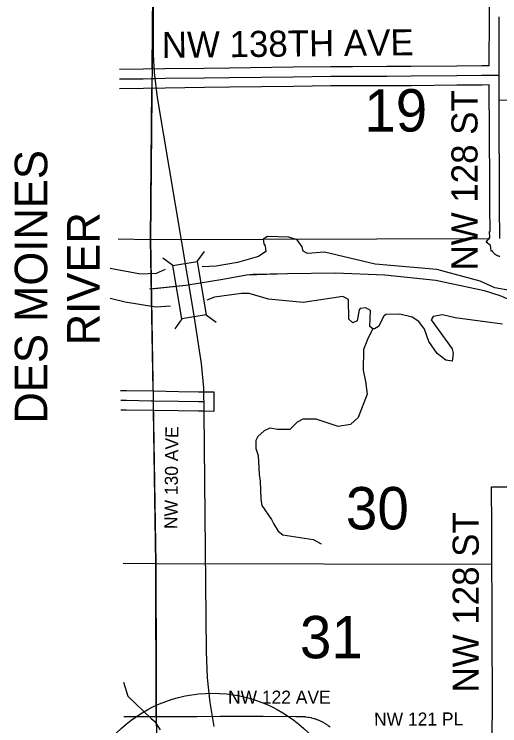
# Model space of a CAD drawing. Extents: x -1403959 to 81668, y -1400582 to 11018.
# Drawn here: x 6176.3 to 6320.4, y 9558.5 to 9769.7 of the extents above; entities that cross this region are included whole.
import ezdxf

# ---------------------------------------------------------------- set-up
doc = ezdxf.new("R2010")
doc.units = 0
for name, color, linetype in [('tdCiCityStreetTxt', 7, 'Continuous'), ('tdCiMapFrame', 7, 'Continuous'), ('tdCiSectLine', 7, 'Continuous'), ('tdCoCityStreetMajor', 7, 'Continuous'), ('tdCoCityStreetMinor', 7, 'Continuous'), ('tdCoClipBndry', 7, 'Continuous'), ('tdCoSecRteCL', 7, 'Continuous'), ('tdCoSectLinePart', 7, 'Continuous'), ('tdCoSectNmbr', 7, 'Continuous'), ('tdCoSurfAsphalt', 7, 'Continuous'), ('tdCoSurfBitum', 7, 'Continuous'), ('tdCoSurfConc', 7, 'Continuous'), ('tdCoTwpNameTxt', 7, 'Continuous')]:
    doc.layers.add(name, color=color, linetype=linetype)

msp = doc.modelspace()

# ---------------------------------------------------------------- linework, layer by layer
at = {"layer": 'tdCiCityStreetTxt'}
for p, q in [((6230.61, 9696.34), (6232.73, 9699.32)), ((6223.4, 9695.14), (6220.42, 9697.26)), ((6223.4, 9695.14), (6230.61, 9696.34)), ((6230.61, 9696.34), (6233.26, 9680.48)), ((6226.05, 9679.27), (6223.4, 9695.14)), ((6223.4, 9695.14), (6223.4, 9695.14)), ((6226.05, 9679.27), (6223.93, 9676.3)), ((6233.26, 9680.48), (6226.05, 9679.27)), ((6233.26, 9680.48), (6236.24, 9678.35))]:
    msp.add_line(p, q, dxfattribs=at)
at = {"layer": 'tdCiMapFrame'}
for points in [[(6320.44, 9703.12), (6320.36, 9712.55), (6320.21, 9744.27), (6320.2, 9751.51), (6320.2, 9751.61), (6320.23, 9768.93)], [(6217.23, 9750.63), (6218.02, 9750.65), (6218.06, 9750.65), (6221.06, 9750.7), (6232.75, 9750.84), (6240.17, 9750.94), (6259.13, 9751.18), (6270.28, 9751.32), (6276.67, 9751.35), (6286.88, 9751.38), (6294.08, 9751.41), (6307.68, 9751.53), (6315.14, 9751.59), (6317.22, 9751.62), (6320.2, 9751.61)], [(6207.52, 9750.53), (6208.5, 9750.53), (6214.6, 9750.59), (6217.23, 9750.63)], [(6320.21, 9744.27), (6329.06, 9743.99)], [(6207.88, 9655.13), (6208.5, 9655.13), (6209.56, 9655.13), (6216.91, 9655)], [(6216.91, 9655), (6217.58, 9654.99)], [(6217.58, 9654.99), (6217.65, 9654.99), (6225.03, 9654.86), (6230.99, 9654.77), (6232.63, 9654.75)]]:
    msp.add_lwpolyline(points, dxfattribs=at)
at = {"layer": 'tdCiSectLine'}
for points in [[(6207.55, 9753.43), (6214.56, 9753.49), (6221.01, 9753.6), (6221.02, 9753.6), (6232.71, 9753.74), (6240.14, 9753.84), (6240.14, 9753.84), (6259.09, 9754.08), (6270.24, 9754.22), (6270.26, 9754.22), (6276.65, 9754.25), (6276.66, 9754.25), (6286.87, 9754.29), (6294.06, 9754.32), (6307.65, 9754.43), (6315.1, 9754.49), (6317.18, 9754.52), (6317.22, 9754.52), (6317.24, 9754.52), (6317.3, 9754.52), (6317.33, 9768.94), (6317.34, 9771.84)], [(6320.48, 9697.76), (6320.29, 9697.8), (6320.11, 9697.85), (6319.93, 9697.92), (6319.79, 9697.99), (6319.62, 9698.07), (6319.59, 9698.08), (6319.42, 9698.17), (6319.26, 9698.27), (6319.11, 9698.38), (6319, 9698.47), (6318.86, 9698.59), (6318.82, 9698.62), (6318.68, 9698.75), (6318.55, 9698.89), (6318.43, 9699.03), (6318.36, 9699.14), (6318.25, 9699.29), (6318.22, 9699.34), (6318.15, 9699.44), (6317.84, 9699.41), (6317.75, 9700.4), (6317.72, 9700.56), (6317.69, 9700.75), (6317.68, 9700.84), (6317.66, 9701.02), (6317.65, 9701.06), (6316.42, 9702.02), (6317.5, 9703.42), (6317.35, 9705.19), (6317.52, 9705.21), (6317.46, 9712.53), (6317.46, 9712.54), (6317.32, 9741.37), (6317.31, 9741.37), (6317.31, 9741.46), (6317.22, 9741.47), (6317.31, 9744.31), (6317.29, 9747.16), (6317.3, 9747.16), (6317.3, 9748.71), (6317.29, 9748.71), (6317.29, 9748.72), (6317.23, 9748.72), (6315.18, 9748.69), (6315.16, 9748.69), (6307.7, 9748.62), (6307.7, 9748.62), (6294.11, 9748.51), (6294.09, 9748.51), (6286.89, 9748.48), (6286.89, 9748.48), (6276.68, 9748.45), (6270.3, 9748.42), (6259.17, 9748.27), (6259.16, 9748.27), (6240.21, 9748.04), (6232.78, 9747.94), (6232.78, 9747.94), (6221.1, 9747.8), (6214.65, 9747.69), (6214.63, 9747.69), (6207.5, 9747.62)], [(6207.83, 9658.03), (6209.56, 9658.03), (6209.61, 9658.03), (6217.7, 9657.89), (6225.08, 9657.76), (6231.03, 9657.67), (6232.65, 9657.65), (6235.55, 9657.63), (6235.5, 9651.82), (6232.6, 9651.85), (6230.97, 9651.86), (6230.95, 9651.86), (6224.98, 9651.96), (6224.98, 9651.96), (6217.6, 9652.09), (6217.6, 9652.09), (6209.53, 9652.23), (6207.93, 9652.23)], [(6318.2, 9556.07), (6318.25, 9564.12), (6318.23, 9571.77), (6318.18, 9580.53), (6318.18, 9580.54), (6318.17, 9588.8), (6318.12, 9596.87), (6318.12, 9596.88), (6318.1, 9605.16), (6318.04, 9612.39), (6318.04, 9612.41), (6318.02, 9620.59), (6317.98, 9626.53), (6317.95, 9629.43), (6323.76, 9629.47)], [(6208.77, 9561.28), (6230.63, 9561.21), (6237.45, 9561.37), (6237.52, 9561.37), (6237.54, 9561.37), (6250.22, 9561.29), (6259.9, 9561.28), (6259.92, 9561.28), (6261.59, 9561.26), (6261.75, 9561.25), (6262.48, 9561.21), (6262.48, 9561.21), (6262.67, 9561.19), (6262.7, 9561.18), (6263.42, 9561.08), (6263.59, 9561.06), (6263.6, 9561.05), (6264.32, 9560.91), (6264.49, 9560.86), (6264.5, 9560.86), (6265.21, 9560.67), (6265.38, 9560.62), (6266.08, 9560.38), (6266.08, 9560.38), (6266.25, 9560.32), (6266.93, 9560.04), (6266.94, 9560.04), (6267.1, 9559.97), (6267.76, 9559.65), (6267.78, 9559.64), (6267.92, 9559.56), (6268.56, 9559.2), (6268.59, 9559.19), (6268.71, 9559.11), (6269.33, 9558.71), (6269.37, 9558.69), (6269.48, 9558.6), (6270.07, 9558.17)]]:
    msp.add_lwpolyline(points, dxfattribs=at)
at = {"layer": 'tdCoCityStreetMajor'}
for points in [[(6217.22, 9753.55), (6217.62, 9799.5)], [(6216.78, 9702.88), (6217.17, 9747.74)], [(6207.11, 9703.04), (6216.78, 9702.88)], [(6216.78, 9702.88), (6317.51, 9703.12)], [(6217.5, 9657.91), (6216.78, 9702.88)], [(6218.33, 9606.68), (6217.6, 9652.11)], [(6208.66, 9606.75), (6218.33, 9606.68)], [(6218.33, 9606.68), (6317.99, 9606.45)], [(6218.33, 9606.68), (6218.44, 9561.27)]]:
    msp.add_lwpolyline(points, dxfattribs=at)
at = {"layer": 'tdCoCityStreetMinor'}
for points in [[(6217.22, 9753.55), (6217.62, 9799.5)], [(6217.5, 9657.91), (6216.78, 9702.88), (6217.17, 9747.74)], [(6218.44, 9561.27), (6218.33, 9606.68), (6217.6, 9652.11)]]:
    msp.add_lwpolyline(points, dxfattribs=at)
at = {"layer": 'tdCoClipBndry'}
for points in [[(6778.71, 10085.37), (6705.52, 10085.58), (6607.92, 10086.06), (6510.34, 10086.5), (6412.84, 10087.26), (6315.56, 10087.31), (6215.78, 10087.65), (6215.21, 10012.23), (6215.81, 9994.41), (6217.04, 9970.57), (6217.41, 9896.62), (6217.06, 9848.03), (6217.62, 9799.5), (6216.78, 9702.88), (6218.33, 9606.68), (6218.57, 9510.16), (6218.52, 9404.76), (6218.61, 9307.34), (6218.13, 9211.25), (6218.14, 9113.22), (6218.14, 9016.46), (6218.02, 8919.84), (6217.44, 8816.34), (6216.99, 8719.3)], [(6217.01, 9688.24), (6227.22, 9689.26), (6238.25, 9691.05), (6245.21, 9692.35), (6257.4, 9692.78), (6271.56, 9693), (6286.3, 9692.31), (6301.47, 9690.76), (6315.83, 9687.72), (6320.39, 9686.18), (6329.92, 9682.23)]]:
    msp.add_lwpolyline(points, dxfattribs=at)
at = {"layer": 'tdCoSecRteCL'}
msp.add_lwpolyline([(6217.64, 9809.12), (6217.49, 9757.74), (6217.86, 9752.44), (6218.72, 9745), (6229.45, 9680.84), (6231.76, 9666.02), (6232.42, 9658.85), (6232.57, 9651.48), (6233.27, 9580.56), (6233.55, 9572.72), (6234.36, 9565.41), (6235.58, 9558.3)], dxfattribs=at)
at = {"layer": 'tdCoSurfAsphalt'}
msp.add_circle((6235.15, 9527.83), 40.33, dxfattribs=at)
at = {"layer": 'tdCoSurfBitum'}
for points in [[(6340.36, 9682.17), (6335.63, 9683.57), (6323.43, 9687.73), (6319, 9688.51), (6314.58, 9690.51), (6301.77, 9693.92), (6283.45, 9695.52), (6268.35, 9699.08), (6263.31, 9698.65), (6262.09, 9699.41), (6261.79, 9700.64), (6260.27, 9702.78), (6257.83, 9703.55), (6251.42, 9703.73), (6250.19, 9702.97), (6250.34, 9701.6), (6250.8, 9700.98), (6250.94, 9699.3), (6248.8, 9697.78), (6242.53, 9695.98), (6236.27, 9694.93), (6232.03, 9694.69)], [(6221.12, 9693.94), (6218.39, 9692.71), (6213.81, 9692.57), (6204.75, 9694.24)], [(6222.7, 9683.01), (6218.36, 9682.79), (6209.2, 9684.2), (6204.75, 9685.35)], [(6282.77, 9676.28), (6281.86, 9677.05), (6282.03, 9681.78), (6280.66, 9682.55), (6278.98, 9682.41), (6278.67, 9681.95), (6278.05, 9678.75), (6276.82, 9678.14), (6275.61, 9679.21), (6275.47, 9685.01), (6273.8, 9685.94), (6262.03, 9684.15), (6251.81, 9685.1), (6246.01, 9686.8), (6243.72, 9686.81), (6235.78, 9685.77), (6233.5, 9684.84)], [(6321.26, 9677.67), (6307.21, 9679.55), (6303.4, 9680.48), (6300.65, 9680.03), (6300.04, 9678.97), (6306.27, 9670.4), (6306.57, 9669.02), (6306.25, 9666.73), (6304.42, 9667.04), (6301.83, 9669.04), (6299.4, 9672.56), (6298.04, 9676.23), (6296.37, 9678.52), (6294.39, 9679.75), (6290.73, 9680.68), (6286.6, 9680.54), (6285.99, 9680.09), (6284.45, 9677.04), (6283.23, 9676.28), (6282.77, 9676.28), (6281.39, 9673.7), (6280, 9670.19), (6279.83, 9664.08), (6280.58, 9660.72), (6281.02, 9656.9), (6278.4, 9650.04), (6276.1, 9647.92), (6272.44, 9647.32), (6265.88, 9649.48), (6261.91, 9649.5), (6260.23, 9648.59), (6258.08, 9646.46), (6254.42, 9646.47), (6252.13, 9646.79), (6250.45, 9646.03), (6248.61, 9644.36), (6247.99, 9643.14), (6247.98, 9640.85), (6248.74, 9638.71), (6249.02, 9633.06), (6249.32, 9631.07), (6249.46, 9625.73), (6249.76, 9623.9), (6252.64, 9619.76), (6253.25, 9618.54), (6254.61, 9616.24), (6255.98, 9615.17), (6264.99, 9613.76), (6267.43, 9612.53)], [(6208.72, 9571.41), (6210, 9567.26), (6217, 9560.51), (6217.92, 9559.9), (6219.59, 9557.3)]]:
    msp.add_lwpolyline(points, dxfattribs=at)
at = {"layer": 'tdCoTwpNameTxt'}
msp.add_lwpolyline([(6216.47, 9688.19), (6227.22, 9689.26), (6238.25, 9691.05), (6245.21, 9692.35), (6247.08, 9692.56), (6257.4, 9692.78), (6271.56, 9693), (6286.3, 9692.31), (6301.47, 9690.76), (6315.83, 9687.72), (6320.39, 9686.18), (6329.92, 9682.23)], dxfattribs=at)

# ---------------------------------------------------------------- texts
at = {"layer": 'tdCoSectLinePart'}
for s, rotation, p in [('19', 359.9884, (6280.17, 9734.9)), ('30', 359.9883, (6274.73, 9616.79)), ('31', 359.9884, (6261.08, 9578.52))]:
    msp.add_text(s, height=12.575, rotation=rotation, dxfattribs=at).set_placement(p)
at = {"layer": 'tdCoSectNmbr'}
for s, height, rotation, p in [('NW 138TH AVE', 7.7382, 0.6151, (6220.13, 9756.74)), ('NW 128 ST', 7.738, 90, (6313.81, 9693.67)), ('NW 130 AVE', 3.869, 89.3622, (6224.7, 9616.88)), ('NW 128 ST', 7.738, 90, (6314.18, 9568.39)), ('NW 122 AVE', 3.869, 359.9176, (6239.74, 9565.08)), ('NW 121 PL', 3.869, 0.1841, (6283.11, 9558.5))]:
    msp.add_text(s, height=height, rotation=rotation, dxfattribs=at).set_placement(p)
at = {"layer": 'tdCoSurfConc'}
for s, p in [('DES MOINES', (6186.09, 9648.18)), ('RIVER', (6201.61, 9671.43))]:
    msp.add_text(s, height=9.673, rotation=89.9874, dxfattribs=at).set_placement(p)

doc.saveas('drawing.dxf')
